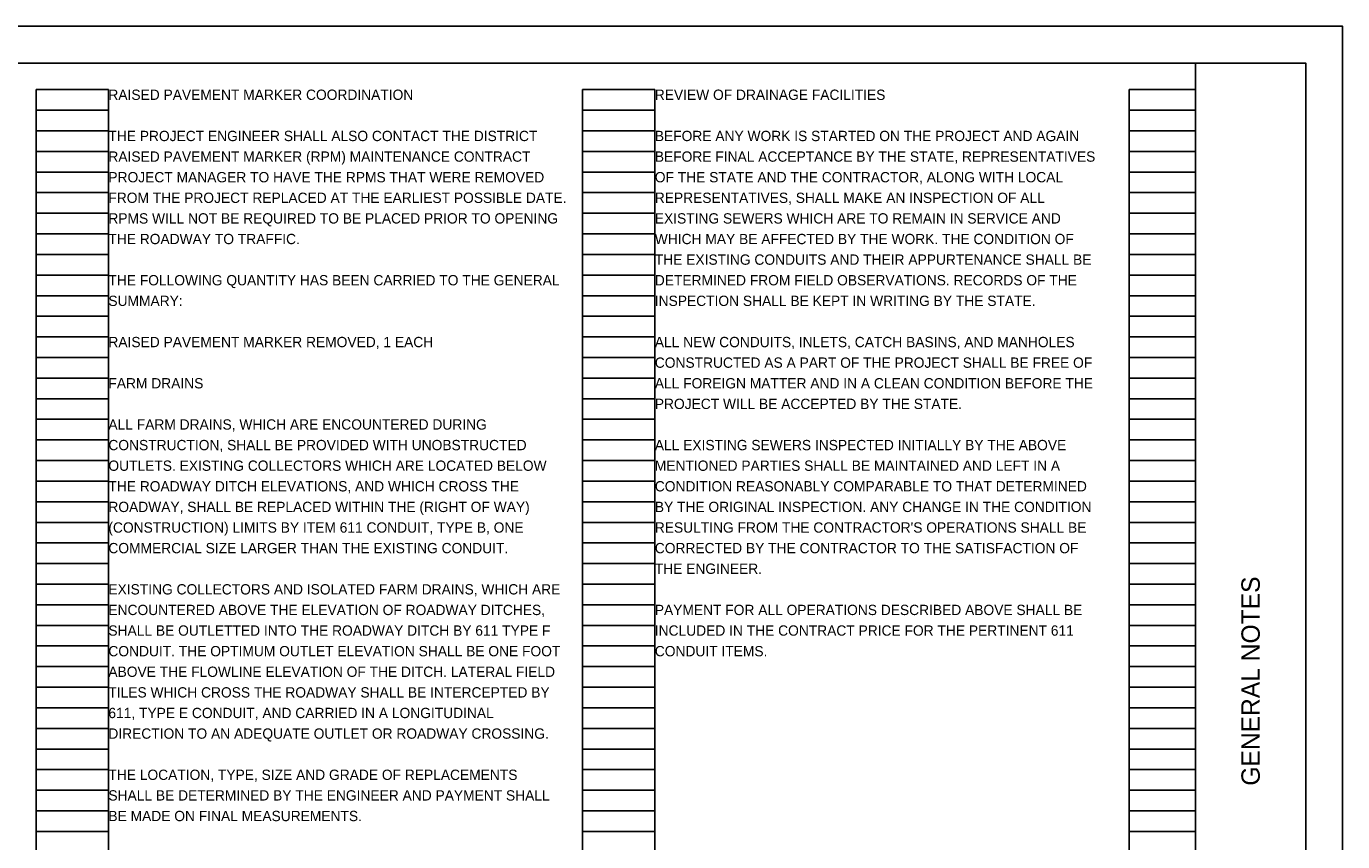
# Model space of a CAD drawing. Extents: x 37.8 to 71.8, y 8.7 to 30.7.
# Drawn here: x 53.88 to 71.76, y 19.59 to 30.67 of the extents above; entities that cross this region are included whole.
import ezdxf

# ---------------------------------------------------------------- set-up
doc = ezdxf.new("R2010")
doc.units = 0
for name, color, linetype in [('SH_Border', 7, 'Continuous'), ('SH_Cut_Line', 7, 'Continuous'), ('SH_Data', 7, 'Continuous'), ('SH_Text', 7, 'Continuous')]:
    doc.layers.add(name, color=color, linetype=linetype)

msp = doc.modelspace()

# ---------------------------------------------------------------- linework, layer by layer
at = {"layer": 'SH_Border'}
msp.add_line((69.759, 9.172), (69.759, 30.172), dxfattribs=at)
msp.add_lwpolyline([(39.259, 30.172), (71.259, 30.172), (71.259, 9.172), (39.259, 9.172)], close=True, dxfattribs=at)
at = {"layer": 'SH_Cut_Line'}
msp.add_lwpolyline([(37.759, 8.672), (71.759, 8.672), (71.759, 30.672), (37.759, 30.672)], close=True, dxfattribs=at)
at = {"layer": 'SH_Data'}
for p, q in [((54.019, 9.652), (54.019, 29.812)), ((54.019, 29.812), (54.999, 29.812)), ((54.999, 9.652), (54.999, 29.812)), ((61.439, 9.652), (61.439, 29.812)), ((61.439, 29.812), (62.419, 29.812)), ((62.419, 9.652), (62.419, 29.812)), ((68.859, 9.652), (68.859, 29.812)), ((68.859, 29.812), (69.759, 29.812)), ((69.759, 9.652), (69.759, 29.812)), ((54.019, 29.532), (54.999, 29.532)), ((61.439, 29.532), (62.419, 29.532)), ((68.859, 29.532), (69.759, 29.532)), ((54.019, 29.252), (54.999, 29.252)), ((61.439, 29.252), (62.419, 29.252)), ((68.859, 29.252), (69.759, 29.252)), ((54.019, 28.972), (54.999, 28.972)), ((61.439, 28.972), (62.419, 28.972)), ((68.859, 28.972), (69.759, 28.972)), ((54.019, 28.692), (54.999, 28.692)), ((61.439, 28.692), (62.419, 28.692)), ((68.859, 28.692), (69.759, 28.692)), ((54.019, 28.412), (54.999, 28.412)), ((61.439, 28.412), (62.419, 28.412)), ((68.859, 28.412), (69.759, 28.412)), ((54.019, 28.132), (54.999, 28.132)), ((61.439, 28.132), (62.419, 28.132)), ((68.859, 28.132), (69.759, 28.132)), ((54.019, 27.852), (54.999, 27.852)), ((61.439, 27.852), (62.419, 27.852)), ((68.859, 27.852), (69.759, 27.852)), ((54.019, 27.572), (54.999, 27.572)), ((61.439, 27.572), (62.419, 27.572)), ((68.859, 27.572), (69.759, 27.572)), ((54.019, 27.292), (54.999, 27.292)), ((61.439, 27.292), (62.419, 27.292)), ((68.859, 27.292), (69.759, 27.292)), ((54.019, 27.012), (54.999, 27.012)), ((61.439, 27.012), (62.419, 27.012)), ((68.859, 27.012), (69.759, 27.012)), ((54.019, 26.732), (54.999, 26.732)), ((61.439, 26.732), (62.419, 26.732)), ((68.859, 26.732), (69.759, 26.732)), ((54.019, 26.452), (54.999, 26.452)), ((61.439, 26.452), (62.419, 26.452)), ((68.859, 26.452), (69.759, 26.452)), ((54.019, 26.172), (54.999, 26.172)), ((61.439, 26.172), (62.419, 26.172)), ((68.859, 26.172), (69.759, 26.172)), ((54.019, 25.892), (54.999, 25.892)), ((61.439, 25.892), (62.419, 25.892)), ((68.859, 25.892), (69.759, 25.892)), ((54.019, 25.612), (54.999, 25.612)), ((61.439, 25.612), (62.419, 25.612)), ((68.859, 25.612), (69.759, 25.612)), ((54.019, 25.332), (54.999, 25.332)), ((61.439, 25.332), (62.419, 25.332)), ((68.859, 25.332), (69.759, 25.332)), ((54.019, 25.052), (54.999, 25.052)), ((61.439, 25.052), (62.419, 25.052)), ((68.859, 25.052), (69.759, 25.052)), ((54.019, 24.772), (54.999, 24.772)), ((61.439, 24.772), (62.419, 24.772)), ((68.859, 24.772), (69.759, 24.772)), ((54.019, 24.492), (54.999, 24.492)), ((61.439, 24.492), (62.419, 24.492)), ((68.859, 24.492), (69.759, 24.492)), ((54.019, 24.212), (54.999, 24.212)), ((61.439, 24.212), (62.419, 24.212)), ((68.859, 24.212), (69.759, 24.212)), ((54.019, 23.932), (54.999, 23.932)), ((61.439, 23.932), (62.419, 23.932)), ((68.859, 23.932), (69.759, 23.932)), ((54.019, 23.652), (54.999, 23.652)), ((61.439, 23.652), (62.419, 23.652)), ((68.859, 23.652), (69.759, 23.652)), ((54.019, 23.372), (54.999, 23.372)), ((61.439, 23.372), (62.419, 23.372)), ((68.859, 23.372), (69.759, 23.372)), ((54.019, 23.092), (54.999, 23.092)), ((61.439, 23.092), (62.419, 23.092)), ((68.859, 23.092), (69.759, 23.092)), ((54.019, 22.812), (54.999, 22.812)), ((61.439, 22.812), (62.419, 22.812)), ((68.859, 22.812), (69.759, 22.812)), ((54.019, 22.532), (54.999, 22.532)), ((61.439, 22.532), (62.419, 22.532)), ((68.859, 22.532), (69.759, 22.532)), ((54.019, 22.252), (54.999, 22.252)), ((61.439, 22.252), (62.419, 22.252)), ((68.859, 22.252), (69.759, 22.252)), ((54.019, 21.972), (54.999, 21.972)), ((61.439, 21.972), (62.419, 21.972)), ((68.859, 21.972), (69.759, 21.972)), ((54.019, 21.692), (54.999, 21.692)), ((61.439, 21.692), (62.419, 21.692)), ((68.859, 21.692), (69.759, 21.692)), ((54.019, 21.412), (54.999, 21.412)), ((61.439, 21.412), (62.419, 21.412)), ((68.859, 21.412), (69.759, 21.412)), ((54.019, 21.132), (54.999, 21.132)), ((61.439, 21.132), (62.419, 21.132)), ((68.859, 21.132), (69.759, 21.132)), ((54.019, 20.852), (54.999, 20.852)), ((61.439, 20.852), (62.419, 20.852)), ((68.859, 20.852), (69.759, 20.852)), ((54.019, 20.572), (54.999, 20.572)), ((61.439, 20.572), (62.419, 20.572)), ((68.859, 20.572), (69.759, 20.572)), ((54.019, 20.292), (54.999, 20.292)), ((61.439, 20.292), (62.419, 20.292)), ((68.859, 20.292), (69.759, 20.292)), ((54.019, 20.012), (54.999, 20.012)), ((61.439, 20.012), (62.419, 20.012)), ((68.859, 20.012), (69.759, 20.012)), ((54.019, 19.732), (54.999, 19.732)), ((61.439, 19.732), (62.419, 19.732)), ((68.859, 19.732), (69.759, 19.732))]:
    msp.add_line(p, q, dxfattribs=at)

# ---------------------------------------------------------------- texts
msp.add_text('GENERAL NOTES', height=0.25, rotation=90, dxfattribs=at).set_placement((70.634, 20.354))
at = {"layer": 'SH_Text'}
for s, p in [('RAISED PAVEMENT MARKER COORDINATION', (54.999, 29.672)), ('REVIEW OF DRAINAGE FACILITIES', (62.419, 29.672)), ('THE PROJECT ENGINEER SHALL ALSO CONTACT THE DISTRICT', (54.999, 29.112)), ('BEFORE ANY WORK IS STARTED ON THE PROJECT AND AGAIN', (62.419, 29.112)), ('RAISED PAVEMENT MARKER (RPM) MAINTENANCE CONTRACT', (54.999, 28.832)), ('BEFORE FINAL ACCEPTANCE BY THE STATE, REPRESENTATIVES', (62.419, 28.832)), ('PROJECT MANAGER TO HAVE THE RPMS THAT WERE REMOVED', (54.999, 28.552)), ('OF THE STATE AND THE CONTRACTOR, ALONG WITH LOCAL', (62.419, 28.552)), ('FROM THE PROJECT REPLACED AT THE EARLIEST POSSIBLE DATE.', (54.999, 28.272)), ('REPRESENTATIVES, SHALL MAKE AN INSPECTION OF ALL', (62.419, 28.272)), ('RPMS WILL NOT BE REQUIRED TO BE PLACED PRIOR TO OPENING', (54.999, 27.992)), ('EXISTING SEWERS WHICH ARE TO REMAIN IN SERVICE AND', (62.419, 27.992)), ('THE ROADWAY TO TRAFFIC.', (54.999, 27.712)), ('WHICH MAY BE AFFECTED BY THE WORK. THE CONDITION OF', (62.419, 27.712)), ('THE EXISTING CONDUITS AND THEIR APPURTENANCE SHALL BE', (62.419, 27.432)), ('THE FOLLOWING QUANTITY HAS BEEN CARRIED TO THE GENERAL', (54.999, 27.152)), ('DETERMINED FROM FIELD OBSERVATIONS. RECORDS OF THE', (62.419, 27.152)), ('SUMMARY:', (54.999, 26.872)), ('INSPECTION SHALL BE KEPT IN WRITING BY THE STATE.', (62.419, 26.872)), ('RAISED PAVEMENT MARKER REMOVED, 1 EACH', (54.999, 26.312)), ('ALL NEW CONDUITS, INLETS, CATCH BASINS, AND MANHOLES', (62.419, 26.312)), ('CONSTRUCTED AS A PART OF THE PROJECT SHALL BE FREE OF', (62.419, 26.032)), ('FARM DRAINS', (54.999, 25.752)), ('ALL FOREIGN MATTER AND IN A CLEAN CONDITION BEFORE THE', (62.419, 25.752)), ('PROJECT WILL BE ACCEPTED BY THE STATE.', (62.419, 25.472)), ('ALL FARM DRAINS, WHICH ARE ENCOUNTERED DURING', (54.999, 25.192)), ('CONSTRUCTION, SHALL BE PROVIDED WITH UNOBSTRUCTED', (54.999, 24.912)), ('ALL EXISTING SEWERS INSPECTED INITIALLY BY THE ABOVE', (62.419, 24.912)), ('OUTLETS. EXISTING COLLECTORS WHICH ARE LOCATED BELOW', (54.999, 24.632)), ('MENTIONED PARTIES SHALL BE MAINTAINED AND LEFT IN A', (62.419, 24.632)), ('THE ROADWAY DITCH ELEVATIONS, AND WHICH CROSS THE', (54.999, 24.352)), ('CONDITION REASONABLY COMPARABLE TO THAT DETERMINED', (62.419, 24.352)), ('ROADWAY, SHALL BE REPLACED WITHIN THE (RIGHT OF WAY)', (54.999, 24.072)), ('BY THE ORIGINAL INSPECTION. ANY CHANGE IN THE CONDITION', (62.419, 24.072)), ('(CONSTRUCTION) LIMITS BY ITEM 611 CONDUIT, TYPE B, ONE', (54.999, 23.792)), ("RESULTING FROM THE CONTRACTOR'S OPERATIONS SHALL BE", (62.419, 23.792)), ('COMMERCIAL SIZE LARGER THAN THE EXISTING CONDUIT.', (54.999, 23.512)), ('CORRECTED BY THE CONTRACTOR TO THE SATISFACTION OF', (62.419, 23.512)), ('THE ENGINEER.', (62.419, 23.232)), ('EXISTING COLLECTORS AND ISOLATED FARM DRAINS, WHICH ARE', (54.999, 22.952)), ('ENCOUNTERED ABOVE THE ELEVATION OF ROADWAY DITCHES,', (54.999, 22.672)), ('PAYMENT FOR ALL OPERATIONS DESCRIBED ABOVE SHALL BE', (62.419, 22.672)), ('SHALL BE OUTLETTED INTO THE ROADWAY DITCH BY 611 TYPE F', (54.999, 22.392)), ('INCLUDED IN THE CONTRACT PRICE FOR THE PERTINENT 611', (62.419, 22.392)), ('CONDUIT. THE OPTIMUM OUTLET ELEVATION SHALL BE ONE FOOT', (54.999, 22.112)), ('CONDUIT ITEMS.', (62.419, 22.112)), ('ABOVE THE FLOWLINE ELEVATION OF THE DITCH. LATERAL FIELD', (54.999, 21.832)), ('TILES WHICH CROSS THE ROADWAY SHALL BE INTERCEPTED BY', (54.999, 21.552)), ('611, TYPE E CONDUIT, AND CARRIED IN A LONGITUDINAL', (54.999, 21.272)), ('DIRECTION TO AN ADEQUATE OUTLET OR ROADWAY CROSSING.', (54.999, 20.992)), ('THE LOCATION, TYPE, SIZE AND GRADE OF REPLACEMENTS', (54.999, 20.432)), ('SHALL BE DETERMINED BY THE ENGINEER AND PAYMENT SHALL', (54.999, 20.152)), ('BE MADE ON FINAL MEASUREMENTS.', (54.999, 19.872))]:
    msp.add_text(s, height=0.14, dxfattribs=at).set_placement(p)

doc.saveas('drawing.dxf')
